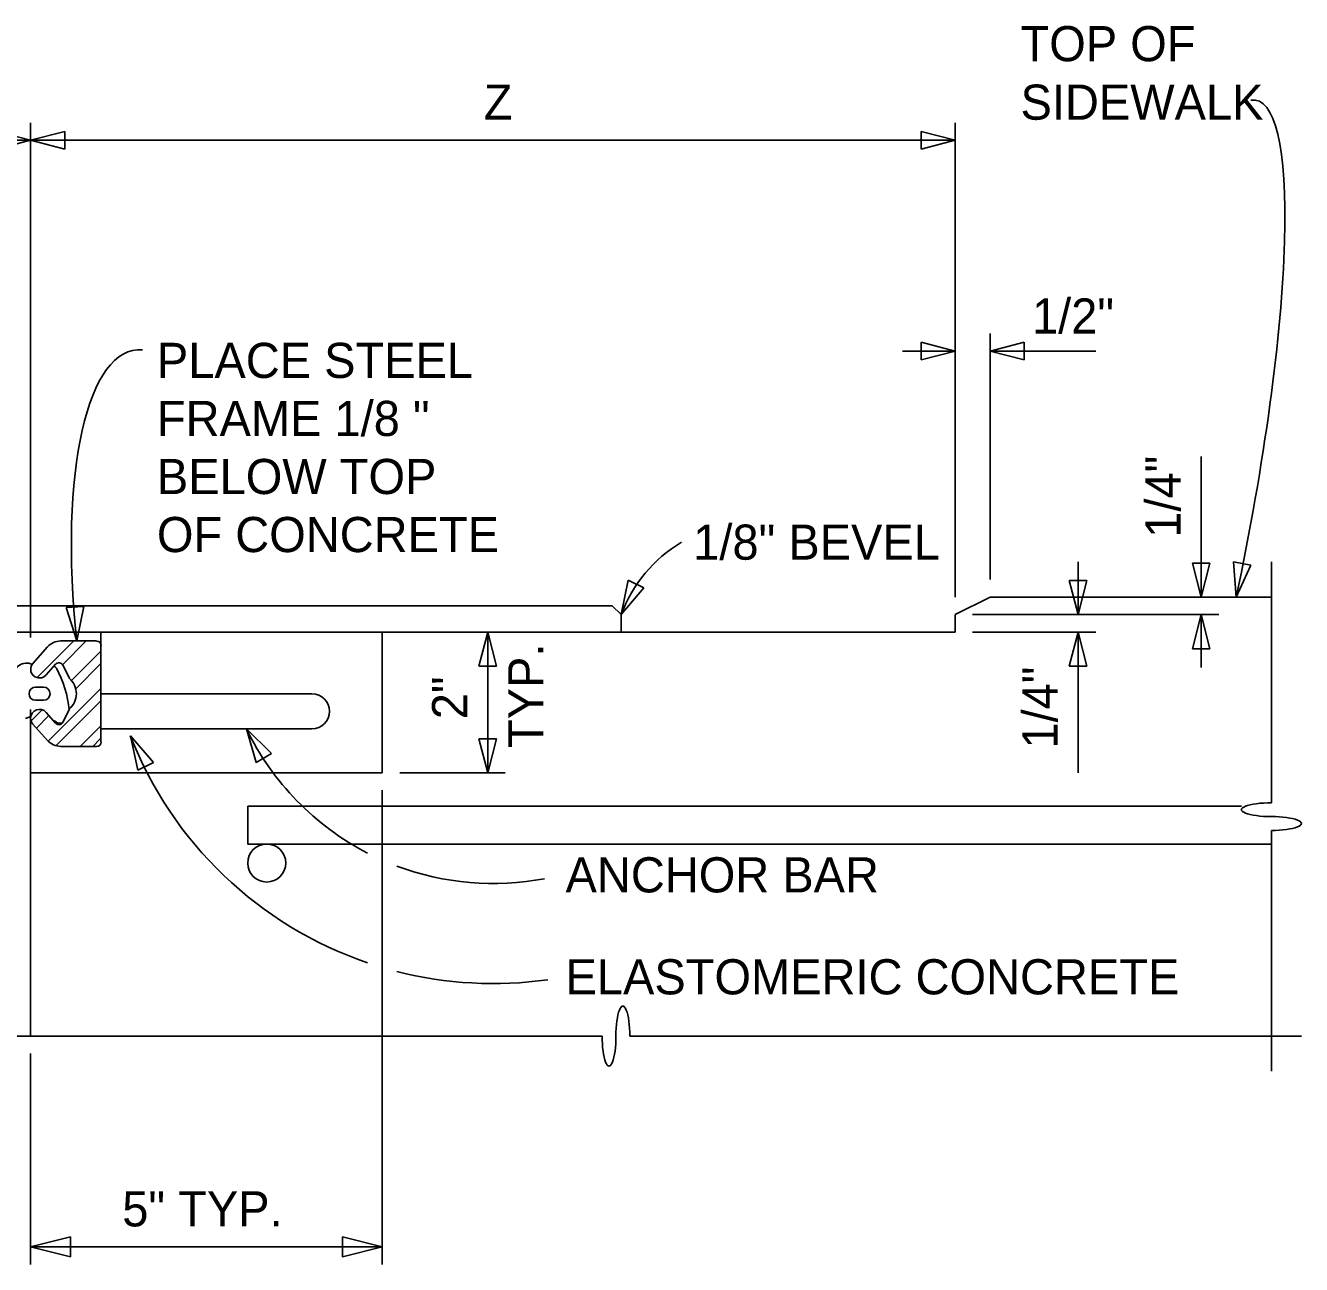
# Model space of a CAD drawing. Extents: x 19590 to 20151, y 19944 to 20103.
# Drawn here: x 19890.8 to 19907.59, y 20053.46 to 20069.77 of the extents above; entities that cross this region are included whole.
import ezdxf

# ---------------------------------------------------------------- set-up
doc = ezdxf.new("R2010")
doc.units = 0
for name, color, linetype in [('Default', 7, 'Continuous'), ('DETAIL_PR', 7, 'Continuous'), ('DETAIL_TEXT_DIMEN_PR', 7, 'Continuous'), ('Level 1', 7, 'Continuous')]:
    doc.layers.add(name, color=color, linetype=linetype)

# ---------------------------------------------------------------- blocks, each defined once
blk = doc.blocks.new('_X7')
at = {"layer": 'Default'}
for p, q in [((8.051, 16.889), (8.594, 17.433)), ((8.426, 17.08), (8.778, 17.433)), ((8.56, 16.847), (8.995, 17.282)), ((8.622, 16.724), (8.995, 17.098)), ((8.213, 15.947), (8.995, 16.729)), ((8.329, 15.879), (8.995, 16.545)), ((7.96, 16.247), (8.125, 16.412)), ((8.04, 16.142), (8.224, 16.326)), ((8.689, 15.87), (8.995, 16.177)), ((8.873, 15.87), (8.995, 15.993))]:
    blk.add_line(p, q, dxfattribs=at)

msp = doc.modelspace()

# ---------------------------------------------------------------- linework, layer by layer
at = {"layer": 'DETAIL_PR'}
for p, q in [((19903.491, 20062.248), (19903.029, 20062.017)), ((19903.491, 20062.248), (19903.029, 20062.017)), ((19903.491, 20062.248), (19907.191, 20062.248)), ((19903.491, 20062.248), (19907.191, 20062.248)), ((19881.985, 20062.133), (19898.519, 20062.133)), ((19881.985, 20062.133), (19898.519, 20062.133)), ((19898.519, 20062.133), (19898.635, 20062.017)), ((19898.519, 20062.133), (19898.635, 20062.017)), ((19898.635, 20062.017), (19898.635, 20061.786)), ((19898.635, 20062.017), (19898.635, 20061.786)), ((19903.029, 20061.786), (19903.029, 20062.017)), ((19903.029, 20061.786), (19903.029, 20062.017)), ((19898.635, 20061.786), (19881.985, 20061.786)), ((19898.635, 20061.786), (19881.985, 20061.786)), ((19891.261, 20061.67), (19891.735, 20061.67)), ((19891.261, 20061.67), (19891.735, 20061.67)), ((19891.792, 20061.612), (19891.792, 20061.786)), ((19891.792, 20061.612), (19891.792, 20061.786)), ((19895.492, 20059.936), (19895.492, 20061.786)), ((19895.492, 20059.936), (19895.492, 20061.786)), ((19903.029, 20061.786), (19898.635, 20061.786)), ((19903.029, 20061.786), (19898.635, 20061.786)), ((19890.896, 20061.376), (19891.087, 20061.592)), ((19890.896, 20061.376), (19891.087, 20061.592)), ((19891.792, 20061.612), (19891.792, 20060.976)), ((19891.792, 20061.612), (19891.792, 20060.976)), ((19891.07, 20061.223), (19891.194, 20061.364)), ((19891.07, 20061.223), (19891.194, 20061.364)), ((19891.376, 20061.18), (19891.289, 20061.352)), ((19891.376, 20061.18), (19891.289, 20061.352)), ((19891.037, 20061.063), (19890.932, 20061.063)), ((19891.037, 20061.063), (19890.932, 20061.063)), ((19891.037, 20060.89), (19890.932, 20060.89)), ((19891.037, 20060.89), (19890.932, 20060.89)), ((19891.792, 20060.976), (19894.567, 20060.976)), ((19891.792, 20060.976), (19891.792, 20060.514)), ((19891.792, 20060.976), (19894.567, 20060.976)), ((19891.792, 20060.976), (19891.792, 20060.514)), ((19890.799, 20060.65), (19890.87, 20060.676)), ((19890.799, 20060.65), (19890.87, 20060.676)), ((19890.867, 20056.47), (19890.867, 20060.769)), ((19890.867, 20056.47), (19890.867, 20060.769)), ((19891.07, 20060.73), (19891.194, 20060.589)), ((19891.07, 20060.73), (19891.194, 20060.589)), ((19891.376, 20060.773), (19891.289, 20060.601)), ((19891.376, 20060.773), (19891.289, 20060.601)), ((19890.896, 20060.577), (19891.087, 20060.361)), ((19890.896, 20060.577), (19891.087, 20060.361)), ((19891.159, 20060.629), (19891.202, 20060.604)), ((19891.159, 20060.629), (19891.202, 20060.604)), ((19891.792, 20060.514), (19894.567, 20060.514)), ((19891.792, 20060.514), (19891.792, 20060.341)), ((19891.792, 20060.514), (19894.567, 20060.514)), ((19891.792, 20060.514), (19891.792, 20060.341)), ((19891.735, 20060.283), (19891.261, 20060.283)), ((19891.735, 20060.283), (19891.261, 20060.283)), ((19890.867, 20059.936), (19895.492, 20059.936)), ((19890.867, 20059.936), (19895.492, 20059.936)), ((19906.796, 20059.498), (19893.723, 20059.498)), ((19893.723, 20059.498), (19893.723, 20058.998)), ((19906.796, 20059.498), (19893.723, 20059.498)), ((19893.723, 20059.498), (19893.723, 20058.998)), ((19907.191, 20058.998), (19893.723, 20058.998)), ((19907.191, 20058.998), (19893.723, 20058.998))]:
    msp.add_line(p, q, dxfattribs=at)
msp.add_circle((19893.973, 20058.748), 0.25, dxfattribs=at)
msp.add_circle((19893.973, 20058.748), 0.25, dxfattribs=at)
for centre, radius, start, end in [((19891.261, 20061.439), 0.231, 90, 138.538), ((19891.261, 20061.439), 0.231, 90, 138.538), ((19891.735, 20061.612), 0.0578, 0, 90), ((19891.735, 20061.612), 0.0578, 0, 90), ((19890.812, 20061.206), 0.173, 64.7625, 184.3545), ((19890.812, 20061.206), 0.173, 64.7625, 184.3545), ((19890.983, 20061.299), 0.116, 138.538, 318.538), ((19890.983, 20061.299), 0.116, 138.538, 318.538), ((19891.155, 20061.283), 0.0578, 28.7472, 73.3345), ((19891.155, 20061.283), 0.0578, 28.7472, 73.3345), ((19891.238, 20061.326), 0.0578, 26.8091, 138.538), ((19891.238, 20061.326), 0.0578, 26.8091, 138.538), ((19889.989, 20060.643), 1.388, 4.9857, 28.7472), ((19889.989, 20060.643), 1.388, 4.9857, 28.7472), ((19891.198, 20060.976), 0.27, 311.1121, 48.8879), ((19891.198, 20060.976), 0.27, 311.1121, 48.8879), ((19890.932, 20060.976), 0.0867, 90, 270), ((19890.932, 20060.976), 0.0867, 90, 270), ((19891.037, 20060.976), 0.0867, 270, 90), ((19891.037, 20060.976), 0.0867, 270, 90), ((19894.567, 20060.745), 0.231, 270, 90), ((19894.567, 20060.745), 0.231, 270, 90), ((19890.983, 20060.654), 0.116, 41.462, 180), ((19890.983, 20060.654), 0.116, 41.462, 180), ((19890.983, 20060.654), 0.116, 180, 221.462), ((19890.983, 20060.654), 0.116, 180, 221.462), ((19891.238, 20060.627), 0.0578, 221.462, 333.1909), ((19891.238, 20060.627), 0.0578, 221.462, 333.1909), ((19891.26, 20060.704), 0.116, 240, 281.5069), ((19891.26, 20060.704), 0.116, 240, 281.5069), ((19891.261, 20060.514), 0.231, 221.462, 270), ((19891.261, 20060.514), 0.231, 221.462, 270), ((19891.735, 20060.341), 0.0578, 270, 0), ((19891.735, 20060.341), 0.0578, 270, 0)]:
    msp.add_arc(centre, radius, start, end, dxfattribs=at)
for centre, major_axis, ratio, start_param, end_param in [((19907.191, 20059.45), (0.395, 0), 0.230204, 1.570796, 4.712389), ((19907.191, 20059.45), (0.395, 0), 0.230204, 1.570796, 4.712389), ((19907.191, 20059.268), (0.395, 0), 0.230206, 4.712389, 7.853982), ((19907.191, 20059.268), (0.395, 0), 0.230206, 4.712389, 7.853982), ((19898.658, 20056.47), (0, -0.395), 0.230204, 1.570796, 4.712389), ((19898.658, 20056.47), (0, -0.395), 0.230204, 1.570796, 4.712389), ((19898.476, 20056.47), (0, -0.395), 0.230206, 4.712389, 7.853982), ((19898.476, 20056.47), (0, -0.395), 0.230206, 4.712389, 7.853982)]:
    msp.add_ellipse(centre, major_axis=major_axis, ratio=ratio, start_param=start_param, end_param=end_param, dxfattribs=at)
at = {"layer": 'DETAIL_TEXT_DIMEN_PR'}
for p, q in [((19890.419, 20068.376), (19890.867, 20068.261)), ((19890.419, 20068.376), (19890.867, 20068.261)), ((19890.867, 20061.717), (19890.867, 20068.492)), ((19890.867, 20061.717), (19890.867, 20068.492)), ((19891.315, 20068.376), (19890.867, 20068.261)), ((19891.315, 20068.376), (19890.867, 20068.261)), ((19891.315, 20068.145), (19891.315, 20068.376)), ((19891.315, 20068.145), (19891.315, 20068.376)), ((19902.581, 20068.145), (19902.581, 20068.376)), ((19902.581, 20068.376), (19903.029, 20068.261)), ((19902.581, 20068.145), (19902.581, 20068.376)), ((19902.581, 20068.376), (19903.029, 20068.261)), ((19903.029, 20062.248), (19903.029, 20068.492)), ((19903.029, 20062.248), (19903.029, 20068.492)), ((19888.46, 20068.261), (19890.867, 20068.261)), ((19888.46, 20068.261), (19890.867, 20068.261)), ((19890.867, 20068.261), (19890.419, 20068.145)), ((19890.867, 20068.261), (19890.419, 20068.145)), ((19903.029, 20068.261), (19890.867, 20068.261)), ((19890.867, 20068.261), (19891.315, 20068.145)), ((19903.029, 20068.261), (19890.867, 20068.261)), ((19890.867, 20068.261), (19891.315, 20068.145)), ((19903.029, 20068.261), (19902.581, 20068.145)), ((19903.029, 20068.261), (19902.581, 20068.145)), ((19903.491, 20062.48), (19903.491, 20065.717)), ((19903.491, 20062.48), (19903.491, 20065.717)), ((19902.581, 20065.37), (19902.581, 20065.601)), ((19902.581, 20065.601), (19903.029, 20065.486)), ((19902.581, 20065.37), (19902.581, 20065.601)), ((19902.581, 20065.601), (19903.029, 20065.486)), ((19903.939, 20065.601), (19903.491, 20065.486)), ((19903.939, 20065.601), (19903.491, 20065.486)), ((19903.939, 20065.37), (19903.939, 20065.601)), ((19903.939, 20065.37), (19903.939, 20065.601)), ((19903.029, 20065.486), (19902.581, 20065.37)), ((19903.029, 20065.486), (19902.581, 20065.37)), ((19903.491, 20065.486), (19903.939, 20065.37)), ((19903.491, 20065.486), (19903.939, 20065.37)), ((19906.151, 20062.696), (19906.382, 20062.696)), ((19906.266, 20062.248), (19906.151, 20062.696)), ((19906.151, 20062.696), (19906.382, 20062.696)), ((19906.266, 20062.248), (19906.151, 20062.696)), ((19906.382, 20062.696), (19906.266, 20062.248)), ((19906.382, 20062.696), (19906.266, 20062.248)), ((19906.693, 20062.71), (19906.921, 20062.669)), ((19906.729, 20062.248), (19906.693, 20062.71)), ((19906.693, 20062.71), (19906.921, 20062.669)), ((19906.729, 20062.248), (19906.693, 20062.71)), ((19906.921, 20062.669), (19906.729, 20062.248)), ((19906.921, 20062.669), (19906.729, 20062.248)), ((19907.191, 20059.541), (19907.191, 20062.711)), ((19907.191, 20059.541), (19907.191, 20062.711)), ((19898.635, 20062.017), (19898.726, 20062.471)), ((19898.635, 20062.017), (19898.726, 20062.471)), ((19898.934, 20062.37), (19898.635, 20062.017)), ((19898.934, 20062.37), (19898.635, 20062.017)), ((19898.726, 20062.471), (19898.934, 20062.37)), ((19898.726, 20062.471), (19898.934, 20062.37)), ((19904.532, 20062.465), (19904.763, 20062.465)), ((19904.648, 20062.017), (19904.532, 20062.465)), ((19904.532, 20062.465), (19904.763, 20062.465)), ((19904.648, 20062.017), (19904.532, 20062.465)), ((19904.763, 20062.465), (19904.648, 20062.017)), ((19904.763, 20062.465), (19904.648, 20062.017)), ((19891.334, 20062.111), (19891.565, 20062.124)), ((19891.334, 20062.111), (19891.565, 20062.124)), ((19891.473, 20061.67), (19891.334, 20062.111)), ((19891.473, 20061.67), (19891.334, 20062.111)), ((19891.565, 20062.124), (19891.473, 20061.67)), ((19891.565, 20062.124), (19891.473, 20061.67)), ((19903.26, 20062.017), (19906.498, 20062.017)), ((19903.26, 20062.017), (19906.498, 20062.017)), ((19906.151, 20061.569), (19906.266, 20062.017)), ((19906.151, 20061.569), (19906.266, 20062.017)), ((19906.266, 20062.017), (19906.382, 20061.569)), ((19906.266, 20062.017), (19906.382, 20061.569)), ((19896.764, 20061.338), (19896.88, 20061.786)), ((19896.764, 20061.338), (19896.88, 20061.786)), ((19896.88, 20059.936), (19896.88, 20061.786)), ((19896.88, 20061.786), (19896.995, 20061.338)), ((19896.88, 20059.936), (19896.88, 20061.786)), ((19896.88, 20061.786), (19896.995, 20061.338)), ((19904.879, 20061.786), (19903.26, 20061.786)), ((19904.879, 20061.786), (19903.26, 20061.786)), ((19904.532, 20061.338), (19904.648, 20061.786)), ((19904.532, 20061.338), (19904.648, 20061.786)), ((19904.648, 20061.786), (19904.763, 20061.338)), ((19904.648, 20061.786), (19904.763, 20061.338)), ((19906.382, 20061.569), (19906.151, 20061.569)), ((19906.382, 20061.569), (19906.151, 20061.569)), ((19896.995, 20061.338), (19896.764, 20061.338)), ((19896.995, 20061.338), (19896.764, 20061.338)), ((19904.763, 20061.338), (19904.532, 20061.338)), ((19904.763, 20061.338), (19904.532, 20061.338)), ((19893.835, 20060.07), (19893.705, 20060.514)), ((19893.705, 20060.514), (19894.034, 20060.189)), ((19893.835, 20060.07), (19893.705, 20060.514)), ((19893.705, 20060.514), (19894.034, 20060.189)), ((19892.275, 20059.969), (19892.179, 20060.422)), ((19892.179, 20060.422), (19892.482, 20060.073)), ((19892.275, 20059.969), (19892.179, 20060.422)), ((19892.179, 20060.422), (19892.482, 20060.073)), ((19896.764, 20060.384), (19896.995, 20060.384)), ((19896.88, 20059.936), (19896.764, 20060.384)), ((19896.764, 20060.384), (19896.995, 20060.384)), ((19896.88, 20059.936), (19896.764, 20060.384)), ((19896.995, 20060.384), (19896.88, 20059.936)), ((19896.995, 20060.384), (19896.88, 20059.936)), ((19894.034, 20060.189), (19893.835, 20060.07)), ((19894.034, 20060.189), (19893.835, 20060.07)), ((19892.482, 20060.073), (19892.275, 20059.969)), ((19892.482, 20060.073), (19892.275, 20059.969)), ((19897.111, 20059.936), (19895.724, 20059.936)), ((19897.111, 20059.936), (19895.724, 20059.936)), ((19895.492, 20053.464), (19895.492, 20059.705)), ((19895.492, 20053.464), (19895.492, 20059.705)), ((19907.191, 20056.008), (19907.191, 20059.177)), ((19907.191, 20056.008), (19907.191, 20059.177)), ((19898.385, 20056.47), (19890.867, 20056.47)), ((19898.385, 20056.47), (19890.867, 20056.47)), ((19898.749, 20056.47), (19907.586, 20056.47)), ((19898.749, 20056.47), (19907.586, 20056.47)), ((19890.867, 20053.464), (19890.867, 20056.239)), ((19890.867, 20053.464), (19890.867, 20056.239)), ((19890.867, 20053.695), (19895.492, 20053.695)), ((19890.867, 20053.695), (19895.492, 20053.695))]:
    msp.add_line(p, q, dxfattribs=at)
for centre, radius, start, end in [((19896.954, 20062.089), 3.611, 205.8637, 242.7252), ((19896.954, 20062.089), 3.611, 205.8637, 242.7252), ((19896.954, 20062.289), 5.128, 201.3572, 251.1723), ((19896.954, 20062.289), 5.128, 201.3572, 251.1723), ((19896.954, 20062.089), 3.611, 249.4192, 280.7711), ((19896.954, 20062.089), 3.611, 249.4192, 280.7711), ((19896.954, 20062.289), 5.128, 255.6669, 278.0265), ((19896.954, 20062.289), 5.128, 255.6669, 278.0265)]:
    msp.add_arc(centre, radius, start, end, dxfattribs=at)
msp.add_ellipse((19892.896, 20061.241), major_axis=(-0.659, 4.259), ratio=0.314674, start_param=6.20772, end_param=7.704615, dxfattribs=at)
msp.add_ellipse((19892.896, 20061.241), major_axis=(-0.659, 4.259), ratio=0.314674, start_param=6.20772, end_param=7.704615, dxfattribs=at)
at = {"layer": 'Level 1'}
for p, q in [((19902.335, 20065.486), (19903.029, 20065.486)), ((19902.335, 20065.486), (19903.029, 20065.486)), ((19904.879, 20065.486), (19903.491, 20065.486)), ((19904.879, 20065.486), (19903.491, 20065.486)), ((19906.266, 20062.248), (19906.266, 20064.098)), ((19906.266, 20062.248), (19906.266, 20064.098)), ((19904.648, 20062.711), (19904.648, 20062.017)), ((19904.648, 20062.711), (19904.648, 20062.017)), ((19906.266, 20061.323), (19906.266, 20062.017)), ((19906.266, 20061.323), (19906.266, 20062.017)), ((19904.648, 20061.786), (19904.648, 20059.936)), ((19904.648, 20061.786), (19904.648, 20059.936)), ((19888.46, 20056.47), (19890.867, 20056.47)), ((19888.46, 20056.47), (19890.867, 20056.47)), ((19890.867, 20053.695), (19891.391, 20053.827)), ((19890.867, 20053.695), (19891.391, 20053.827)), ((19891.391, 20053.827), (19891.391, 20053.563)), ((19891.391, 20053.827), (19891.391, 20053.563)), ((19894.968, 20053.827), (19895.492, 20053.695)), ((19894.968, 20053.563), (19894.968, 20053.827)), ((19894.968, 20053.827), (19895.492, 20053.695)), ((19894.968, 20053.563), (19894.968, 20053.827)), ((19891.391, 20053.563), (19890.867, 20053.695)), ((19891.391, 20053.563), (19890.867, 20053.695)), ((19895.492, 20053.695), (19894.968, 20053.563)), ((19895.492, 20053.695), (19894.968, 20053.563))]:
    msp.add_line(p, q, dxfattribs=at)
msp.add_arc((19900.388, 20061.365), 1.87, 120.8358, 159.6044, dxfattribs=at)
msp.add_arc((19900.388, 20061.365), 1.87, 120.8358, 159.6044, dxfattribs=at)
msp.add_ellipse((19905.614, 20062.36), major_axis=(1.377, 6.428), ratio=0.169331, start_param=4.731306, end_param=6.346137, dxfattribs=at)
msp.add_ellipse((19905.614, 20062.36), major_axis=(1.377, 6.428), ratio=0.169331, start_param=4.731306, end_param=6.346137, dxfattribs=at)

# ---------------------------------------------------------------- block references
at = {"layer": 'DETAIL_PR', "xscale": 0.8880107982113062, "yscale": 0.8880107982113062}
msp.add_blockref('_X7', (19883.804, 20046.19), dxfattribs=at)
msp.add_blockref('_X7', (19883.804, 20046.19), dxfattribs=at)

# ---------------------------------------------------------------- texts
at = {"layer": 'DETAIL_TEXT_DIMEN_PR'}
for s, height, p in [('TOP OF', 0.4625, (19903.89, 20069.301)), ('TOP OF', 0.4625, (19903.89, 20069.301)), ('Z', 0.462, (19896.827, 20068.531)), ('Z', 0.462, (19896.827, 20068.531)), ('SIDEWALK', 0.4625, (19903.89, 20068.531)), ('SIDEWALK', 0.4625, (19903.89, 20068.531)), ('PLACE STEEL', 0.4625, (19892.528, 20065.132)), ('PLACE STEEL', 0.4625, (19892.528, 20065.132)), ('FRAME 1/8 " ', 0.4625, (19892.528, 20064.368)), ('FRAME 1/8 " ', 0.4625, (19892.528, 20064.368)), ('BELOW TOP ', 0.4625, (19892.528, 20063.604)), ('BELOW TOP ', 0.4625, (19892.528, 20063.604)), ('OF CONCRETE', 0.4625, (19892.528, 20062.84)), ('OF CONCRETE', 0.4625, (19892.528, 20062.84)), ('1/8" BEVEL', 0.4625, (19899.584, 20062.74)), ('1/8" BEVEL', 0.4625, (19899.584, 20062.74)), ('ANCHOR BAR', 0.4625, (19897.904, 20058.361)), ('ANCHOR BAR', 0.4625, (19897.904, 20058.361)), ('ELASTOMERIC CONCRETE', 0.4625, (19897.904, 20057.019)), ('ELASTOMERIC CONCRETE', 0.4625, (19897.904, 20057.019)), ('5" TYP.', 0.4625, (19892.072, 20053.965)), ('5" TYP.', 0.4625, (19892.072, 20053.965))]:
    msp.add_text(s, height=height, dxfattribs=at).set_placement(p)
for s, rotation, p in [('1/2"', 360, (19904.041, 20065.717)), ('1/2"', 360, (19904.041, 20065.717)), ('1/4"', 90, (19905.996, 20063.029)), ('1/4"', 90, (19905.996, 20063.029)), ('TYP.', 90, (19897.612, 20060.262)), ('TYP.', 90, (19897.612, 20060.262)), ('2"', 90, (19896.61, 20060.64)), ('2"', 90, (19896.61, 20060.64)), ('1/4"', 90, (19904.378, 20060.254)), ('1/4"', 90, (19904.378, 20060.254))]:
    msp.add_text(s, height=0.4625, rotation=rotation, dxfattribs=at).set_placement(p)

doc.saveas('drawing.dxf')
